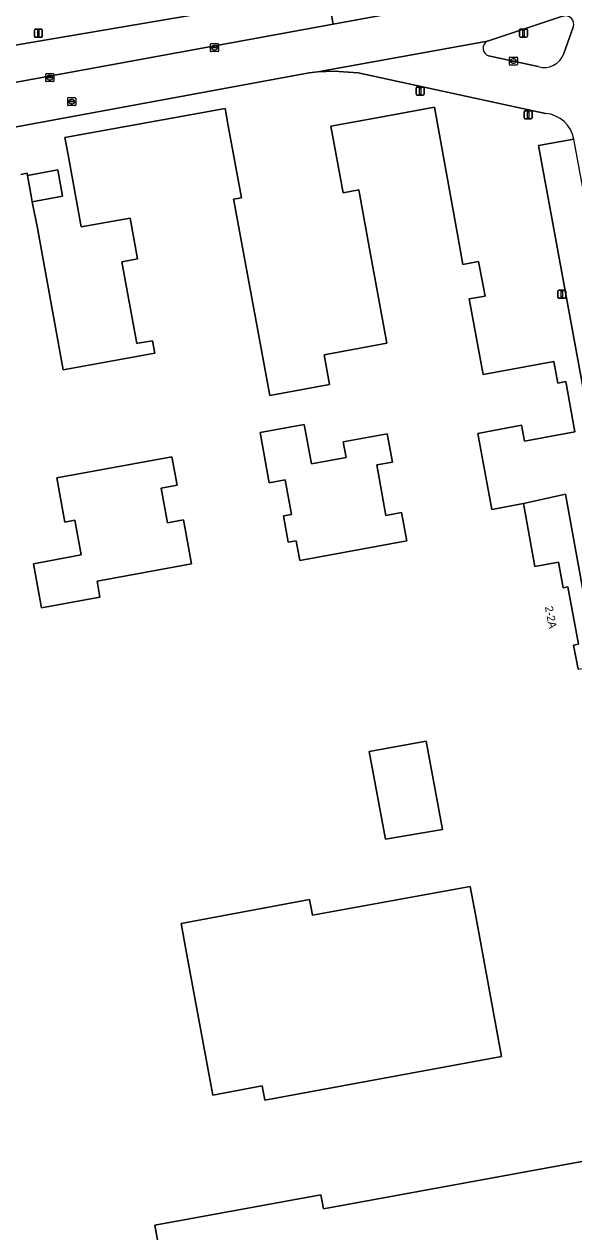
# Model space of a CAD drawing. Extents: x 159451 to 160664, y 388402 to 389723.
# Drawn here: x 159578.8 to 159647.4, y 388939.8 to 389090.8 of the extents above; entities that cross this region are included whole.
import ezdxf

# ---------------------------------------------------------------- set-up
doc = ezdxf.new("R2010")
doc.units = 0
for name, color, linetype in [('IMGEO_Berm_groen', 7, 'Continuous'), ('IMGEO_Brandkraan', 7, 'Continuous'), ('IMGEO_Erf', 7, 'Continuous'), ('IMGEO_Groenvoorziening', 7, 'Continuous'), ('IMGEO_Kolk', 7, 'Continuous'), ('IMGEO_Lichtmast', 7, 'Continuous'), ('IMGEO_Pand', 7, 'Continuous'), ('IMGEO_Pand_nummerreeks', 7, 'Continuous'), ('IMGEO_Pand_overbouw', 7, 'Continuous'), ('IMGEO_Parkeervlak_open', 7, 'Continuous'), ('IMGEO_Rijbaan_lokaal_open', 7, 'Continuous')]:
    doc.layers.add(name, color=color, linetype=linetype)

msp = doc.modelspace()

# ---------------------------------------------------------------- linework, layer by layer
at = {"layer": 'IMGEO_Berm_groen'}
for points in [[(159646.05, 389091.76), (159636.67, 389088.64)], [(159646.19, 389087.09), (159647.37, 389090.39)], [(159636.79, 389086.83), (159642.98, 389085.47)]]:
    msp.add_lwpolyline(points, dxfattribs=at)
for centre, radius, start, end in [((159646.39, 389090.77), 1.05, 339.2112, 108.8324), ((159637.06, 389087.76), 0.965, 113.8265, 254.0704), ((159643.76, 389087.92), 2.56, 252.2313, 341.2695)]:
    msp.add_arc(centre, radius, start, end, dxfattribs=at)
at = {"layer": 'IMGEO_Brandkraan'}
for p, q in [((159584.2, 389080.67), (159584.2, 389081.52)), ((159584.27, 389081.6), (159585.13, 389081.6)), ((159584.46, 389081.09), (159584.46, 389081.1)), ((159584.5, 389081.14), (159584.9, 389081.14)), ((159584.9, 389081.05), (159584.5, 389081.05)), ((159584.69, 389081.37), (159584.71, 389081.37)), ((159584.71, 389080.82), (159584.69, 389080.82)), ((159584.94, 389081.1), (159584.94, 389081.09)), ((159585.2, 389081.52), (159585.2, 389080.67)), ((159585.13, 389080.59), (159584.27, 389080.59))]:
    msp.add_line(p, q, dxfattribs=at)
for points in [[(159584.2, 389080.67), (159584.2, 389081.52)], [(159584.27, 389081.6), (159585.13, 389081.6)], [(159585.2, 389081.52), (159585.2, 389080.67)], [(159585.13, 389080.59), (159584.27, 389080.59)]]:
    msp.add_lwpolyline(points, dxfattribs=at)
for centre, radius, start, end in [((159584.28, 389081.52), 0.0765, 91.552, 178.448), ((159584.28, 389081.52), 0.0765, 91.552, 178.448), ((159584.5, 389081.1), 0.0403, 85.8775, 175.7526), ((159584.5, 389081.09), 0.0366, 178.938, 274.7102), ((159584.9, 389081.1), 0.0386, 1.7309, 96.639), ((159584.9, 389081.09), 0.043, 264.8664, 352.4533), ((159585.12, 389081.52), 0.0765, 1.552, 88.448), ((159585.12, 389081.52), 0.0765, 1.552, 88.448), ((159584.28, 389080.67), 0.0765, 181.552, 268.448), ((159584.28, 389080.67), 0.0765, 181.552, 268.448), ((159585.12, 389080.67), 0.0765, 271.552, 358.448), ((159585.12, 389080.67), 0.0765, 271.552, 358.448)]:
    msp.add_arc(centre, radius, start, end, dxfattribs=at)
for centre, major_axis, ratio, start_param, end_param in [((159584.69, 389081.09), (-0.387, 0.002), 0.722429, 4.712389, 7.853982), ((159584.71, 389081.09), (-0.39, 0.002), 0.717154, 1.570796, 4.712389)]:
    msp.add_ellipse(centre, major_axis=major_axis, ratio=ratio, start_param=start_param, end_param=end_param, dxfattribs=at)
at = {"layer": 'IMGEO_Erf'}
for points in [[(159643.92, 389079.62), (159620.48, 389084.7), (159617.46, 389084.91), (159615.44, 389084.83), (159614.39, 389084.68), (159577.34, 389077.87)], [(159578.34, 389072), (159579.13, 389072.15), (159579.18, 389071.87), (159582.95, 389072.57), (159583.56, 389069.29), (159579.77, 389068.59), (159580.42, 389065.27), (159583.65, 389047.57), (159593.27, 389049.32), (159595.08, 389049.65), (159594.8, 389051.22), (159592.98, 389050.89), (159592.83, 389050.86), (159590.96, 389061.09), (159592.93, 389061.45), (159592, 389066.55), (159585.88, 389065.44), (159584.24, 389074.44), (159583.85, 389076.61), (159603.87, 389080.25), (159604.27, 389078.06), (159605.9, 389069.09), (159604.92, 389068.91), (159604.96, 389068.72), (159609.44, 389044.37), (159616.91, 389045.75), (159616.23, 389049.44), (159624.09, 389050.89), (159621.92, 389062.68), (159620.6, 389070.06), (159618.62, 389069.7), (159617.09, 389078.01), (159622.84, 389079.07), (159630.05, 389080.4), (159632.85, 389064.75), (159633.57, 389060.76), (159635.55, 389061.13), (159636.35, 389056.8), (159634.37, 389056.44), (159636.1, 389047), (159644.95, 389048.62), (159645.44, 389045.92), (159646.44, 389046.1), (159647.59, 389039.81), (159641.28, 389038.66), (159640.92, 389040.64), (159635.45, 389039.64), (159637.19, 389030.11), (159641.14, 389030.86), (159646.4, 389032.02), (159648.46, 389020.78)], [(159655.43, 389033.15), (159655.09, 389034.96), (159650.65, 389034.14), (159643.02, 389075.63), (159647.45, 389076.41)], [(159651.67, 388949.22), (159616.15, 388942.71), (159615.83, 388944.49), (159595.07, 388940.7), (159596.42, 388933.23), (159609.16, 388924.47), (159610.51, 388924.73), (159611.5, 388919.55), (159611.62, 388919.57), (159611.8, 388918.56), (159649.98, 388924.44)]]:
    msp.add_lwpolyline(points, dxfattribs=at)
for points in [[(159613.2, 389023.76), (159626.58, 389026.21), (159625.93, 389029.75), (159623.96, 389029.39), (159622.81, 389035.69), (159624.78, 389036.05), (159624.13, 389039.59), (159618.62, 389038.58), (159618.98, 389036.61), (159614.65, 389035.82), (159613.75, 389040.74), (159608.24, 389039.73), (159609.39, 389033.47), (159611.36, 389033.83), (159612.15, 389029.51), (159611.16, 389029.33), (159611.77, 389026.02), (159612.75, 389026.2)], [(159588.23, 389019.18), (159587.87, 389021.15), (159599.67, 389023.32), (159598.66, 389028.82), (159596.69, 389028.46), (159595.89, 389032.79), (159597.86, 389033.15), (159597.21, 389036.69), (159582.85, 389034.06), (159583.86, 389028.55), (159585.08, 389028.77), (159585.88, 389024.44), (159579.93, 389023.35), (159580.94, 389017.84)], [(159649.76, 389013.67), (159648.46, 389020.78), (159646.4, 389032.02), (159641.14, 389030.86), (159642.58, 389022.99), (159645.53, 389023.53), (159646.12, 389020.34), (159646.7, 389020.45), (159648.01, 389013.28), (159647.42, 389013.18), (159647.99, 389010.15), (159649.02, 389010.33), (159653.81, 388982.89), (159654.68, 388983.05), (159657.91, 388965.29), (159658.57, 388965.49)], [(159631.02, 388990.13), (159629.01, 389001.17), (159621.86, 388999.88), (159623.93, 388988.91)], [(159635.15, 388979.49), (159634.49, 388983.01), (159614.79, 388979.41), (159614.42, 388981.4), (159611.73, 388980.9), (159598.37, 388978.37), (159599.09, 388974.46), (159602.33, 388956.93), (159608.52, 388958.08), (159608.85, 388956.31), (159638.42, 388961.77)]]:
    msp.add_lwpolyline(points, close=True, dxfattribs=at)
msp.add_arc((159643.56, 389075.68), 3.96, 10.6192, 84.6847, dxfattribs=at)
at = {"layer": 'IMGEO_Groenvoorziening'}
msp.add_lwpolyline([(159516.65, 389000), (159504.91, 389075.55), (159505.31, 389078.14), (159506.99, 389079.73), (159534.92, 389087.14), (159543.41, 389088.84), (159556.65, 389090.59), (159574.7, 389093.29), (159575.64, 389087.81), (159616.62, 389094.8), (159617.37, 389090.77), (159624.2, 389092.03), (159623.3, 389096.87), (159619.74, 389102.13), (159610.54, 389099.97), (159603.08, 389098.71), (159550.31, 389091.49), (159531.42, 389088.06), (159524.66, 389086.44), (159511.44, 389082.95), (159506.07, 389081.38)], dxfattribs=at)
at = {"layer": 'IMGEO_Kolk'}
for p, q in [((159602.12, 389088.34), (159602.97, 389088.34)), ((159602.05, 389087.42), (159602.05, 389088.27)), ((159602.97, 389087.34), (159602.12, 389087.34)), ((159602.3, 389087.84), (159602.3, 389087.85)), ((159602.74, 389087.8), (159602.34, 389087.8)), ((159602.35, 389087.89), (159602.75, 389087.89)), ((159602.53, 389088.12), (159602.56, 389088.12)), ((159602.56, 389087.56), (159602.53, 389087.56)), ((159602.79, 389087.85), (159602.79, 389087.84)), ((159603.05, 389088.27), (159603.05, 389087.42)), ((159639.4, 389085.74), (159639.4, 389086.59)), ((159639.47, 389086.67), (159640.32, 389086.67)), ((159640.32, 389085.67), (159639.47, 389085.67)), ((159639.65, 389086.16), (159639.65, 389086.17)), ((159640.09, 389086.12), (159639.69, 389086.12)), ((159639.7, 389086.21), (159640.1, 389086.21)), ((159639.88, 389086.45), (159639.91, 389086.45)), ((159639.91, 389085.89), (159639.88, 389085.89)), ((159640.14, 389086.17), (159640.14, 389086.16)), ((159640.4, 389086.59), (159640.4, 389085.74)), ((159581.47, 389083.67), (159581.47, 389084.53)), ((159581.54, 389084.6), (159582.39, 389084.6)), ((159581.72, 389084.09), (159581.72, 389084.11)), ((159582.16, 389084.06), (159581.76, 389084.06)), ((159581.77, 389084.14), (159582.17, 389084.14)), ((159581.95, 389084.38), (159581.98, 389084.38)), ((159581.98, 389083.82), (159581.95, 389083.82)), ((159582.21, 389084.11), (159582.21, 389084.09)), ((159582.47, 389084.53), (159582.47, 389083.67)), ((159582.39, 389083.6), (159581.54, 389083.6))]:
    msp.add_line(p, q, dxfattribs=at)
for points in [[(159602.12, 389088.34), (159602.97, 389088.34)], [(159602.05, 389087.42), (159602.05, 389088.27)], [(159602.97, 389087.34), (159602.12, 389087.34)], [(159603.05, 389088.27), (159603.05, 389087.42)], [(159639.4, 389085.74), (159639.4, 389086.59)], [(159639.47, 389086.67), (159640.32, 389086.67)], [(159640.32, 389085.67), (159639.47, 389085.67)], [(159640.4, 389086.59), (159640.4, 389085.74)], [(159581.47, 389083.67), (159581.47, 389084.53)], [(159581.54, 389084.6), (159582.39, 389084.6)], [(159582.47, 389084.53), (159582.47, 389083.67)], [(159582.39, 389083.6), (159581.54, 389083.6)]]:
    msp.add_lwpolyline(points, dxfattribs=at)
for centre, radius, start, end in [((159602.12, 389088.27), 0.0765, 91.552, 178.448), ((159602.12, 389088.27), 0.0765, 91.552, 178.448), ((159602.97, 389088.27), 0.0765, 1.552, 88.448), ((159602.97, 389088.27), 0.0765, 1.552, 88.448), ((159602.12, 389087.42), 0.0765, 181.552, 268.448), ((159602.12, 389087.42), 0.0765, 181.552, 268.448), ((159602.35, 389087.85), 0.0403, 85.8775, 175.7526), ((159602.34, 389087.84), 0.0366, 178.938, 274.7102), ((159602.75, 389087.84), 0.043, 264.8664, 352.4533), ((159602.75, 389087.85), 0.0386, 1.7309, 96.639), ((159602.97, 389087.42), 0.0765, 271.552, 358.448), ((159602.97, 389087.42), 0.0765, 271.552, 358.448), ((159639.47, 389086.59), 0.0765, 91.552, 178.448), ((159639.47, 389086.59), 0.0765, 91.552, 178.448), ((159639.47, 389085.74), 0.0765, 181.552, 268.448), ((159639.47, 389085.74), 0.0765, 181.552, 268.448), ((159639.7, 389086.17), 0.0403, 85.8775, 175.7526), ((159639.69, 389086.16), 0.0366, 178.938, 274.7102), ((159640.1, 389086.17), 0.043, 264.8664, 352.4533), ((159640.1, 389086.17), 0.0386, 1.7309, 96.639), ((159640.32, 389086.59), 0.0765, 1.552, 88.448), ((159640.32, 389086.59), 0.0765, 1.552, 88.448), ((159640.32, 389085.74), 0.0765, 271.552, 358.448), ((159640.32, 389085.74), 0.0765, 271.552, 358.448), ((159581.54, 389084.52), 0.0765, 91.552, 178.448), ((159581.54, 389084.52), 0.0765, 91.552, 178.448), ((159581.77, 389084.1), 0.0403, 85.8775, 175.7526), ((159581.76, 389084.09), 0.0366, 178.938, 274.7102), ((159582.17, 389084.1), 0.043, 264.8664, 352.4533), ((159582.17, 389084.1), 0.0386, 1.7309, 96.639), ((159582.39, 389084.52), 0.0765, 1.552, 88.448), ((159582.39, 389084.52), 0.0765, 1.552, 88.448), ((159581.54, 389083.67), 0.0765, 181.552, 268.448), ((159581.54, 389083.67), 0.0765, 181.552, 268.448), ((159582.39, 389083.67), 0.0765, 271.552, 358.448), ((159582.39, 389083.67), 0.0765, 271.552, 358.448)]:
    msp.add_arc(centre, radius, start, end, dxfattribs=at)
for centre, major_axis, ratio, start_param, end_param in [((159602.53, 389087.84), (-0.387, 0.002), 0.722429, 4.712389, 7.853982), ((159602.56, 389087.84), (-0.39, 0.002), 0.717154, 1.570796, 4.712389), ((159639.88, 389086.17), (-0.387, 0.002), 0.722429, 4.712389, 7.853982), ((159639.91, 389086.17), (-0.39, 0.002), 0.717154, 1.570796, 4.712389), ((159581.95, 389084.1), (-0.387, 0.002), 0.722429, 4.712389, 7.853982), ((159581.98, 389084.1), (-0.39, 0.002), 0.717154, 1.570796, 4.712389)]:
    msp.add_ellipse(centre, major_axis=major_axis, ratio=ratio, start_param=start_param, end_param=end_param, dxfattribs=at)
at = {"layer": 'IMGEO_Lichtmast'}
for p, q in [((159580.04, 389089.23), (159580.04, 389090.03)), ((159580.04, 389090.03), (159580.04, 389089.23)), ((159580.14, 389090.13), (159580.93, 389090.13)), ((159580.93, 389090.13), (159580.14, 389090.13)), ((159581.03, 389090.03), (159581.03, 389089.23)), ((159581.03, 389089.23), (159581.03, 389090.03)), ((159640.65, 389089.26), (159640.65, 389090.06)), ((159640.65, 389090.06), (159640.65, 389089.26)), ((159640.75, 389090.16), (159641.54, 389090.16)), ((159641.54, 389090.16), (159640.75, 389090.16)), ((159641.64, 389090.06), (159641.64, 389089.26)), ((159641.64, 389089.26), (159641.64, 389090.06)), ((159580.93, 389089.13), (159580.14, 389089.13)), ((159580.14, 389089.13), (159580.93, 389089.13)), ((159641.54, 389089.16), (159640.75, 389089.16)), ((159640.75, 389089.16), (159641.54, 389089.16)), ((159627.74, 389082.01), (159627.74, 389082.81)), ((159627.74, 389082.81), (159627.74, 389082.01)), ((159627.84, 389082.91), (159628.63, 389082.91)), ((159628.63, 389082.91), (159627.84, 389082.91)), ((159628.73, 389082.81), (159628.73, 389082.01)), ((159628.73, 389082.01), (159628.73, 389082.81)), ((159628.63, 389081.91), (159627.84, 389081.91)), ((159627.84, 389081.91), (159628.63, 389081.91)), ((159641.24, 389079.05), (159641.24, 389079.85)), ((159641.24, 389079.85), (159641.24, 389079.05)), ((159641.34, 389079.95), (159642.13, 389079.95)), ((159642.13, 389079.95), (159641.34, 389079.95)), ((159642.23, 389079.85), (159642.23, 389079.05)), ((159642.23, 389079.05), (159642.23, 389079.85)), ((159642.13, 389078.95), (159641.34, 389078.95)), ((159641.34, 389078.95), (159642.13, 389078.95)), ((159645.46, 389056.62), (159645.46, 389057.42)), ((159645.46, 389057.42), (159645.46, 389056.62)), ((159645.56, 389057.52), (159646.35, 389057.52)), ((159646.35, 389057.52), (159645.56, 389057.52)), ((159646.45, 389057.42), (159646.45, 389056.62)), ((159646.45, 389056.62), (159646.45, 389057.42)), ((159646.35, 389056.52), (159645.56, 389056.52)), ((159645.56, 389056.52), (159646.35, 389056.52))]:
    msp.add_line(p, q, dxfattribs=at)
for points in [[(159580.46, 389090.01), (159580.61, 389090.01), (159580.61, 389089.26), (159580.46, 389089.26), (159580.46, 389090.01)], [(159641.07, 389090.03), (159641.22, 389090.03), (159641.22, 389089.28), (159641.07, 389089.28), (159641.07, 389090.03)], [(159628.16, 389082.79), (159628.31, 389082.79), (159628.31, 389082.04), (159628.16, 389082.04), (159628.16, 389082.79)], [(159641.66, 389079.83), (159641.81, 389079.83), (159641.81, 389079.08), (159641.66, 389079.08), (159641.66, 389079.83)], [(159645.88, 389057.4), (159646.03, 389057.4), (159646.03, 389056.65), (159645.88, 389056.65), (159645.88, 389057.4)]]:
    msp.add_lwpolyline(points, dxfattribs=at)
for centre, start, end in [((159580.14, 389090.03), 90, 180), ((159580.14, 389090.03), 90, 180), ((159580.93, 389090.03), 0, 90), ((159580.93, 389090.03), 360, 90), ((159640.75, 389090.06), 90, 180), ((159640.75, 389090.06), 90, 180), ((159641.54, 389090.06), 0, 90), ((159641.54, 389090.06), 360, 90), ((159580.14, 389089.23), 180, 270), ((159580.14, 389089.23), 180, 270), ((159580.93, 389089.23), 270, 0), ((159580.93, 389089.23), 270, 0), ((159640.75, 389089.26), 180, 270), ((159640.75, 389089.26), 180, 270), ((159641.54, 389089.26), 270, 0), ((159641.54, 389089.26), 270, 0), ((159627.84, 389082.81), 90, 180), ((159627.84, 389082.81), 90, 180), ((159628.63, 389082.81), 0, 90), ((159628.63, 389082.81), 360, 90), ((159627.84, 389082.01), 180, 270), ((159627.84, 389082.01), 180, 270), ((159628.63, 389082.01), 270, 0), ((159628.63, 389082.01), 270, 0), ((159641.34, 389079.85), 90, 180), ((159641.34, 389079.85), 90, 180), ((159642.13, 389079.85), 0, 90), ((159642.13, 389079.85), 360, 90), ((159641.34, 389079.05), 180, 270), ((159641.34, 389079.05), 180, 270), ((159642.13, 389079.05), 270, 0), ((159642.13, 389079.05), 270, 0), ((159645.56, 389057.42), 90, 180), ((159645.56, 389057.42), 90, 180), ((159646.35, 389057.42), 0, 90), ((159646.35, 389057.42), 360, 90), ((159645.56, 389056.62), 180, 270), ((159645.56, 389056.62), 180, 270), ((159646.35, 389056.62), 270, 0), ((159646.35, 389056.62), 270, 0)]:
    msp.add_arc(centre, 0.1, start, end, dxfattribs=at)
at = {"layer": 'IMGEO_Pand'}
for points in [[(159647.99, 389010.15), (159647.42, 389013.18), (159648.01, 389013.28), (159646.7, 389020.45), (159646.12, 389020.34), (159645.53, 389023.53), (159642.58, 389022.99), (159641.14, 389030.86), (159637.19, 389030.11), (159635.45, 389039.64), (159640.92, 389040.64), (159641.28, 389038.66), (159647.59, 389039.81), (159646.44, 389046.1), (159645.44, 389045.92), (159644.95, 389048.62), (159636.1, 389047), (159634.37, 389056.44), (159636.35, 389056.8), (159635.55, 389061.13), (159633.57, 389060.76), (159632.85, 389064.75), (159630.05, 389080.4), (159622.84, 389079.07), (159617.09, 389078.01), (159618.62, 389069.7), (159620.6, 389070.06), (159621.92, 389062.68), (159624.09, 389050.89), (159616.23, 389049.44), (159616.91, 389045.75), (159609.44, 389044.37), (159604.96, 389068.72), (159604.92, 389068.91), (159605.9, 389069.09), (159604.27, 389078.06), (159603.87, 389080.25), (159583.85, 389076.61), (159584.24, 389074.44), (159585.88, 389065.44), (159592, 389066.55), (159592.93, 389061.45), (159590.96, 389061.09), (159592.83, 389050.86), (159592.98, 389050.89), (159594.8, 389051.22), (159595.08, 389049.65), (159593.27, 389049.32), (159583.65, 389047.57), (159580.42, 389065.27), (159579.77, 389068.59), (159579.68, 389069.05), (159579.18, 389071.87), (159579.13, 389072.15), (159578.34, 389072)], [(159596.42, 388933.23), (159595.07, 388940.7), (159615.83, 388944.49), (159616.15, 388942.71), (159651.67, 388949.22)]]:
    msp.add_lwpolyline(points, dxfattribs=at)
for points in [[(159579.18, 389071.87), (159579.68, 389069.05), (159579.77, 389068.59), (159583.56, 389069.29), (159582.95, 389072.57)], [(159612.75, 389026.2), (159611.77, 389026.02), (159611.16, 389029.33), (159612.15, 389029.51), (159611.36, 389033.83), (159609.39, 389033.47), (159608.24, 389039.73), (159613.75, 389040.74), (159614.65, 389035.82), (159618.98, 389036.61), (159618.62, 389038.58), (159624.13, 389039.59), (159624.78, 389036.05), (159622.81, 389035.69), (159623.96, 389029.39), (159625.93, 389029.75), (159626.58, 389026.21), (159613.2, 389023.76)], [(159580.94, 389017.84), (159579.93, 389023.35), (159585.88, 389024.44), (159585.08, 389028.77), (159583.86, 389028.55), (159582.85, 389034.06), (159597.21, 389036.69), (159597.86, 389033.15), (159595.89, 389032.79), (159596.69, 389028.46), (159598.66, 389028.82), (159599.67, 389023.32), (159587.87, 389021.15), (159588.23, 389019.18)], [(159629.01, 389001.17), (159631.02, 388990.13), (159623.93, 388988.91), (159621.86, 388999.88)], [(159634.49, 388983.01), (159635.15, 388979.49), (159638.42, 388961.77), (159608.85, 388956.31), (159608.52, 388958.08), (159602.33, 388956.93), (159599.09, 388974.46), (159598.37, 388978.37), (159611.73, 388980.9), (159614.42, 388981.4), (159614.79, 388979.41)]]:
    msp.add_lwpolyline(points, close=True, dxfattribs=at)
at = {"layer": 'IMGEO_Pand_overbouw'}
msp.add_lwpolyline([(159658.57, 388965.49), (159649.76, 389013.67), (159648.46, 389020.78), (159646.4, 389032.02), (159641.14, 389030.86), (159642.58, 389022.99), (159645.53, 389023.53), (159646.12, 389020.34), (159646.7, 389020.45), (159648.01, 389013.28), (159647.42, 389013.18), (159647.99, 389010.15), (159649.02, 389010.33), (159653.81, 388982.89), (159654.68, 388983.05), (159657.91, 388965.29)], close=True, dxfattribs=at)
at = {"layer": 'IMGEO_Parkeervlak_open'}
for points in [[(159617.37, 389090.77), (159616.62, 389094.8), (159575.64, 389087.81), (159576.42, 389083.26)], [(159647.45, 389076.41), (159643.02, 389075.63), (159650.65, 389034.14), (159655.09, 389034.96)]]:
    msp.add_lwpolyline(points, close=True, dxfattribs=at)
at = {"layer": 'IMGEO_Rijbaan_lokaal_open'}
msp.add_lwpolyline([(159663.46, 389099.3), (159666.97, 389101.23), (159676.44, 389106.81), (159673.66, 389111.55), (159671.93, 389110.52), (159664.76, 389106.28), (159657.65, 389102.44), (159652.95, 389100.29), (159649.12, 389098.65), (159644.65, 389097.04), (159639.1, 389095.34), (159630.64, 389093.3), (159624.2, 389092.03), (159617.37, 389090.77), (159576.42, 389083.26), (159577.34, 389077.87), (159614.39, 389084.68), (159615.44, 389084.83), (159636.67, 389088.64), (159646.05, 389091.76), (159646.13, 389091.79), (159655.4, 389095.03)], close=True, dxfattribs=at)
for points in [[(159647.37, 389090.39), (159646.19, 389087.09)], [(159636.67, 389088.64), (159615.44, 389084.83), (159617.46, 389084.91), (159620.48, 389084.7), (159643.92, 389079.62)], [(159642.98, 389085.47), (159636.79, 389086.83)]]:
    msp.add_lwpolyline(points, dxfattribs=at)
for centre, radius, start, end in [((159646.39, 389090.77), 1.05, 339.2112, 108.8324), ((159637.06, 389087.76), 0.965, 113.8265, 254.0704), ((159643.76, 389087.92), 2.56, 252.2313, 341.2695), ((159643.56, 389075.68), 3.96, 10.6192, 84.6847)]:
    msp.add_arc(centre, radius, start, end, dxfattribs=at)

# ---------------------------------------------------------------- texts
at = {"layer": 'IMGEO_Pand_nummerreeks'}
msp.add_text('2-2A', height=1, rotation=280.5709, dxfattribs=at).set_placement((159643.83, 389017.95))

doc.saveas('drawing.dxf')
